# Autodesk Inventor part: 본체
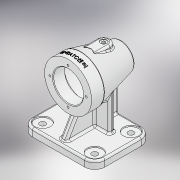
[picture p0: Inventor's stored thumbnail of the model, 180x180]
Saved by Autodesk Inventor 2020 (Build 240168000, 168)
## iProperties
Created: 2024-12
Part Number: 본체
Material: 알루미늄 6061
Document SubType Name: Modeling
Designer: 1강의실14
Mass: 739.317 g
Surface Area: 673.92 cm^2
Volume: 273.821 cm^3
Density: 2.7 g/cm^3
Appearance: 알루미늄 - 평지
Author: 1강의실14
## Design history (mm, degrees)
sketch "스케치1"
  geometry: L1 (37, -28)-(0, -28); L2 (0, -28)-(0, 56); L3 (0, 56)-(37, 56); L4 (37, 56)-(37, -28); L5 (37, 56)-(37, 36); L6 (37, 36)-(21, -28); L7 (21.096, -7)-(32.346, 38); L8 (23.5, 56)-(23.5, 38); L9 (23.5, 38)-(32.346, 38); L10 (21.096, -7)-(17.5, -7); L11 (17.5, -7)-(17.5, -17); L12 (17.5, -17)-(15.5, -17); L13 (15.5, -17)-(15.5, -20); L14 (15.5, -20)-(0, -20); L15 (21, -28)-(0, -28); L16 (37, 56)-(23.5, 56); 1 further point
  constraints: 32 end point, 5 perpendicular, 5 point on line, 4 horizontal, 2 parallel, 1 collinear, 1 vertical
  dimensions: "d0" = 74 diameter of L4 L2; "d1" = 84 distance of L1.end L2.end; "d2" = 56 distance from line of point (0, 0) L3; "d3" = 20 distance of L3.end L5.end; "d4" = 42 diameter of L6.end L2; "d5" = 5 distance between parallel lines of L6 L7; "d6" = 35 diameter of L11 L2; "d8" = 31 diameter of L13 L2; "d9" = 3 distance between parallel lines of L12 L14; "d10" = 10 distance between parallel lines of L10 L12; "d11" = 18 distance from line of L8.start L9; "d12" = 47 diameter of L8 L2; "d13" = 45 distance between parallel lines of L9 L10
revolve "회전1" sketch "스케치1" stored, may be unused: angle "d14" = 90 deg
sketch "스케치2" dims "d15" = 57
  geometry: C1 r 23.5 at (0, 0) reference; 3 further points
  constraints: 2 vertical alignment, 1 coincident, 2 other
hole "구멍1" sketch "스케치2" at (0, 28.5) diameter "d16" = 3.242; stored, may be unused: countersink angle "d20" = 90 deg, drill point angle "d22" = 120 deg; dims "d17" = 8, "d18" = 4, "d19" = 2, "d21" = 10
node "작업 평면1"
sketch "스케치3"
  geometry: L1 (-37, 56)-(37, 56) reference; L2 (10, 0)-(10, 29.345); L3 (10, 29.345)-(-10, 29.345); L4 (-10, 0)-(-10, 29.345); A1 r 10 centre (0, 0) between (10, 0) and (-10, 0); 1 further point
  constraints: 6 end point, 2 perpendicular, 2 point on circle, 2 tangent, 1 centre point, 1 coincident, 1 vertical
  dimensions: "d27" = 20 diameter of A1; "d28" = 56 distance from line of L1 A1.centre
extrude "돌출1" join sketch "스케치3" distance "d29" = 9.12908; taper "d30" = 0 deg
sketch "스케치11"
  geometry: L1 (-23.5, 38)-(23.5, 38) reference; L2 (-32.346, 38)-(32.346, 38) reference; L3 (0, 38)-(-32.346, 38); L4 (-21.096, -7)-(-32.346, 38) reference; L5 (-21.096, -7)-(0, -7); L6 (-17.5, -7)-(17.5, -7) reference; L7 (0, -7)-(0, 38); L8 (-37, 36)-(37, 36) reference; 3 further points
  constraints: 6 end point, 2 midpoint, 1 collinear, 1 perpendicular, 1 point on line
revolve "회전2" sketch "스케치11" stored, may be unused: angle "d91" = 90 deg
sketch "스케치4"
  geometry: C1 r 5 at (0, 0); A1 r 10 centre (0, 0) between (10, 0) and (-10, 0) reference; 1 further point
  constraints: 1 centre point, 1 coincident
  dimensions: "d31" = 10 diameter of C1
extrude "돌출2" cut sketch "스케치4" distance "d32" = 1; taper "d33" = 0 deg
sketch "스케치5"
  geometry: C1 r 5 at (0, 0) reference; 2 further points
  constraints: 1 coincident
hole "구멍2" sketch "스케치5" at (0, 0) diameter "d34" = 5.1881; stored, may be unused: countersink angle "d38" = 90 deg, drill point angle "d40" = 120 deg; dims "d35" = 12, "d36" = 4, "d37" = 2, "d39" = 23
node "작업 평면2"
sketch "스케치6"
  geometry: L1 (57, -18)-(-57, -18); L2 (-57, -18)-(-57, 71); L3 (-57, 71)-(57, 71); L4 (57, 71)-(57, -18); L5 (-21, -28)-(21, -28) reference; 1 further point
  constraints: 8 end point, 2 parallel, 1 horizontal, 1 perpendicular
  dimensions: "d42" = 99 distance between parallel lines of L5 L3; "d43" = 89 distance of L1.end L2.end; "d44" = 114 distance of L2.end L3.end; "d45" = 57 distance from line of point (0, 0) L4
extrude "돌출3" join sketch "스케치6" distance "d46" = 12; taper "d47" = 0 deg
sketch "스케치7"
  geometry: L1 (57, 18)-(-57, 18) reference; 5 further points
  constraints: 2 horizontal alignment, 2 vertical alignment
  dimensions: "d48" = 16 distance from line of L1 point (41, 2); "d49" = 82 distance of point (41, 2) point (-41, 2); "d50" = 41 horizontal distance of point (0, 0) point (-41, 2); "d51" = 57 distance of point (41, -55) point (41, 2)
hole "구멍3" sketch "스케치7" at (41, 2), (-41, 2), (-41, -55), (41, -55) diameter "d52" = 9; stored, may be unused: countersink angle "d56" = 90 deg, drill point angle "d58" = 120 deg; dims "d53" = 12, "d54" = 24, "d55" = 2, "d57" = 23
sketch "스케치8"
  geometry: L1 (-28, -11)-(28, -11); L2 (28, -11)-(28, -19); L3 (28, -19)-(-28, -19); L4 (-28, -19)-(-28, -11); L5 (-5, 18)-(5, 18); L6 (5, 18)-(5, -64); L7 (5, -64)-(-5, -64); L8 (-5, -64)-(-5, 18); L9 (57, 18)-(-57, 18) reference; L10 (-57, -71)-(57, -71) reference; 1 further point
  constraints: 16 end point, 4 parallel, 2 horizontal, 2 perpendicular, 1 collinear
  dimensions: "d59" = 56 distance of L2.end L3.end; "d60" = 8 distance of L1.end L2.end; "d61" = 10 distance of L6.end L7.end; "d62" = 5 distance from line of point (0, 0) L8; "d63" = 29 distance between parallel lines of L9 L1; "d64" = 28 distance from line of point (0, 0) L4; "d65" = 7 distance between parallel lines of L10 L7
extrude "돌출4" join sketch "스케치8" stored distance "d66" = 56; taper "d67" = 0 deg
extrude "돌출5" join sketch "스케치8" stored distance "d68" = 56; taper "d69" = 0 deg
sketch "스케치9"
  geometry: L1 (-37, 56)-(-37, 36) reference; L2 (-37, 44.947)-(-70, 64); L3 (-70, 67)-(-70, 43) reference; L4 (-82, 71)-(-70, 71) reference; L5 (-70, -18)-(-70, 71) reference; 1 further point
  constraints: 2 end point, 2 point on line
  dimensions: "d70" = 7 distance from line of L4 L2.end; "d72" = 60 deg angle of L3 L2
feature "리브1" sketch "스케치9" dims "d73" = 1, "d74" = 10, "d75" = 0, "d76" = 0, "d77" = 1, "d78" = 1
fillet "모깎기1" dims "d79" = 3
node "작업 평면4"
sketch "스케치10"
  geometry: L1 (-37, 10)-(37, 10) reference; 2 further points
  constraints: 1 vertical alignment, 1 other
  dimensions: "d80" = 9 distance from line of L1 point (0, 1)
feature "엠보싱1" sketch "스케치10" dims "d0" = 74, "d1" = 84, "d2" = 56, "d3" = 20, "d4" = 42, "d5" = 5, "d6" = 35, "d8" = 31, "d9" = 3, "d10" = 10, "d11" = 18, "d12" = 47, "d13" = 45, "d81" = 0.5, "d82" = 0
chamfer "모따기1" distance "d83" = 1; stored, may be unused: second distance "d84" = 2, angle "d85" = 45 deg
fillet "모깎기2" dims "d86" = 16
fillet "모깎기3" dims "d87" = 5
fillet "모깎기4" dims "d88" = 3
fillet "모깎기5" dims "d89" = 3
fillet "모깎기6" dims "d90" = 3
fillet "모깎기7" dims "d92" = 0.3
node "솔리드1"
pattern_circular "원형 패턴1" dims angle "d24" = 360 deg
feature "A9D066F2-1C7D-4E18-AEED-F7BC21143FA4" dims "d52" = 9, "d53" = 12, "d54" = 24, "d55" = 2, "d56" = 90 deg, "d57" = 23, "d58" = 120 deg
other parameters: "d26" = 33, "d41" = -82
